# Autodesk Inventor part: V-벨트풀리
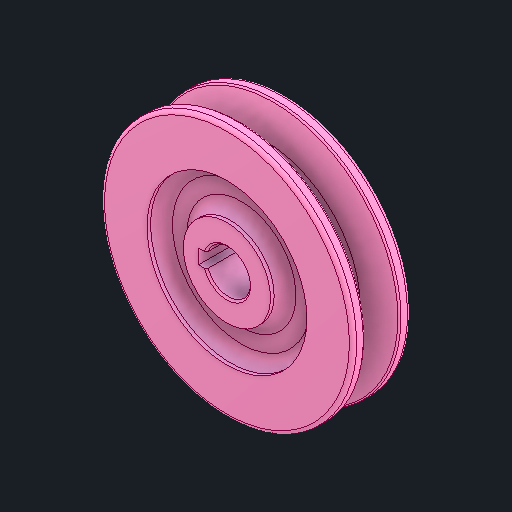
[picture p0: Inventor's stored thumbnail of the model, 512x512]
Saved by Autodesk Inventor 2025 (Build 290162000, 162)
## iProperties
Created: 2025-08
Part Number: V-벨트풀리
Material: 강철, 연강
Document SubType Name: Modeling
Designer: infra14
Density: 7.86 g/cm^3
Appearance: 기본값
Author: jhkim
Sending System: Autodesk Inventor 2026
Preprocessor: ST-DEVELOPER v20.1
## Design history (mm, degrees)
feature "Solid1"
node "솔리드1"
